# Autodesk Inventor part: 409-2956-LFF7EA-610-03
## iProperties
Created: 2011-01
Part Number: 409-2956-LFF7EA-610-03
Cost Center: 0 lbmass
Material: A36 STEEL PLATE
Document SubType Name: Sheet Metal
Designer: S. Boerckel
Authority: 0 in^3
Mass: 3042.95 g
Surface Area: 706.45 cm^2
Volume: 387.144 cm^3
Density: 7.86 g/cm^3
Flat Pattern Width: 11.43 cm
Flat Pattern Length: 26.67 cm
Flat Pattern Area: 304.838 cm^2
Sheet Metal Rule: 1/2"Thk
Description: BASE PLATE
SaveDate: 2008-01-15
SaveTime: 10:24
FileName: Sheet Metal
Wide: =<Flat Pattern Width>cm
Length: =<Flat Pattern Length>cm
Thickness: 0.5000 in
SMR: =<Sheet Metal Rule> - <Material>
Author: S. Boerckel
Revision Number: 0
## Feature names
1. Plate1
